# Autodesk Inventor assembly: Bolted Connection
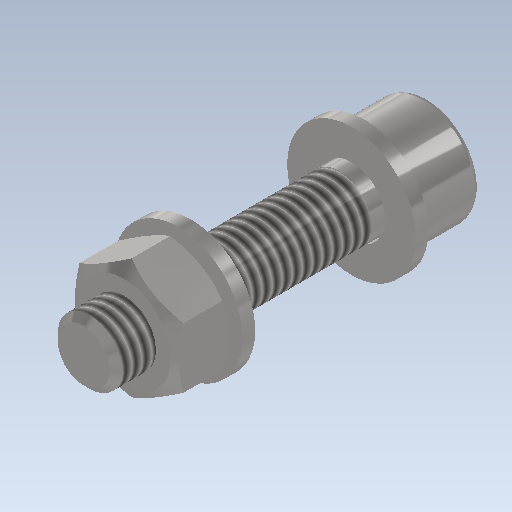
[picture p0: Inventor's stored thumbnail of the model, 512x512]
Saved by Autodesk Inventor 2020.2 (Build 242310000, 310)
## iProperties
ClientObjectVersion: 1
Created: 2020-01
Part Number: Bolted Connection
Document SubType Name: Assembly
Designer: thira
Author: thira
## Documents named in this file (4)
- C:\Users\thira\OneDrive\เดสก์ท็อป\INV-01 Intro to Modeling_2020\Wheel Assem Final V1\Wheel Assy_Joint\Design Accelerator\Bolted Connection2.iam
- C:\Users\thira\OneDrive\เอกสาร\Inventor\Content Center Files\R2020\en-US\ISO 7089\ISO 7089 - 8 - 140 HV(1).ipt
- C:\Users\thira\OneDrive\เอกสาร\Inventor\Content Center Files\R2020\en-US\ISO 4762(2)\ISO 4762 - M8 x 35ISO.ipt
- C:\Users\thira\OneDrive\เอกสาร\Inventor\Content Center Files\R2020\en-US\ISO 4032(2)\ISO 4032 - M8 - ISO.ipt
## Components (4 placed, 3 different names)
1. ISO 7089 8:1
2. ISO 4762 M8 x 35:1
3. ISO 7089 8:2
4. ISO 4032 M8:1
